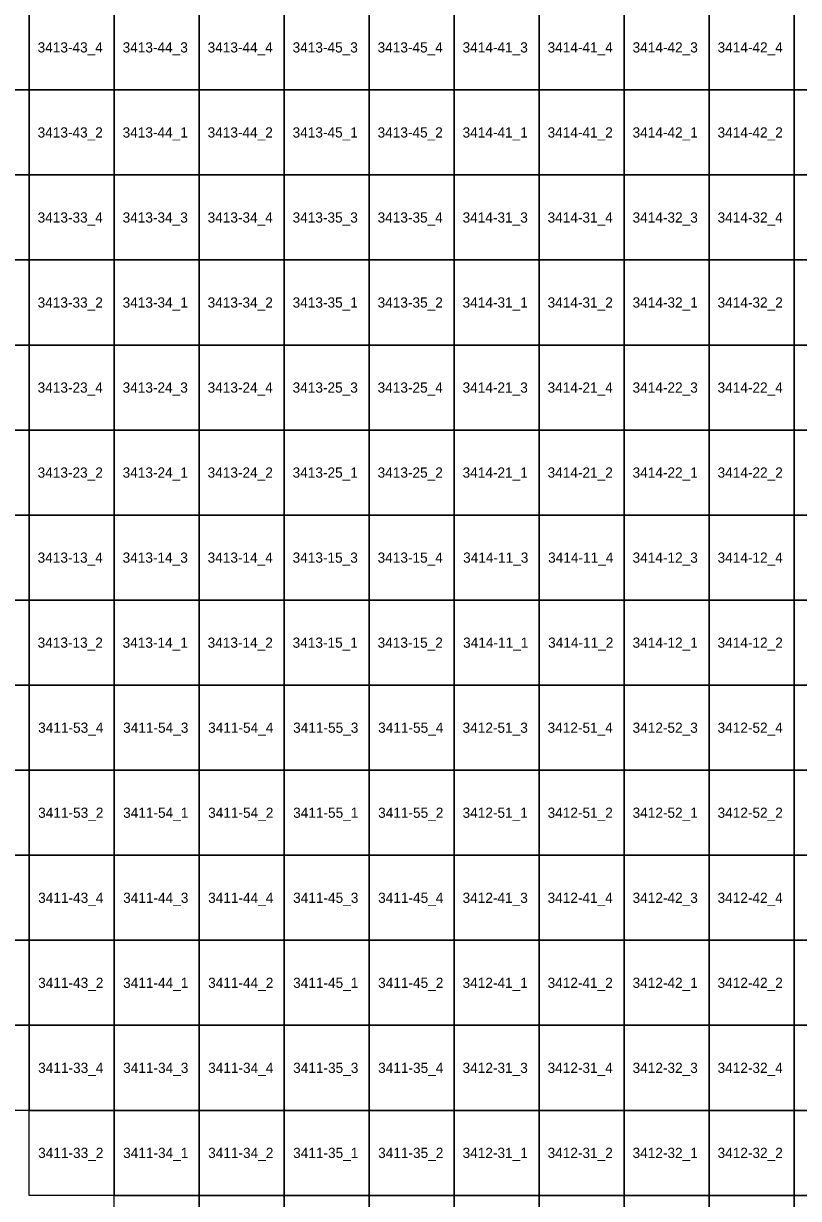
# Model space of a CAD drawing. Extents: x 312500 to 765000, y 172500 to 440000.
# Drawn here: x 612332 to 635129, y 209909 to 244452 of the extents above; entities that cross this region are included whole.
import ezdxf

# ---------------------------------------------------------------- set-up
doc = ezdxf.new("R2010")
doc.units = 0
doc.layers.add('Topo5_ramis_TKS2025', color=7, linetype='Continuous')
doc.layers.add('Topo5_ramis_TKS2025_Nr', color=7, linetype='Continuous')

msp = doc.modelspace()

# ---------------------------------------------------------------- linework, layer by layer
at = {"layer": 'Topo5_ramis_TKS2025'}
for points in [[(610000, 242500), (610000, 245000), (612500, 245000), (612500, 242500), (610000, 242500)], [(612500, 242500), (612500, 245000), (615000, 245000), (615000, 242500), (612500, 242500)], [(615000, 242500), (615000, 245000), (617500, 245000), (617500, 242500), (615000, 242500)], [(617500, 242500), (617500, 245000), (620000, 245000), (620000, 242500), (617500, 242500)], [(620000, 242500), (620000, 245000), (622500, 245000), (622500, 242500), (620000, 242500)], [(622500, 242500), (622500, 245000), (625000, 245000), (625000, 242500), (622500, 242500)], [(625000, 242500), (625000, 245000), (627500, 245000), (627500, 242500), (625000, 242500)], [(627500, 242500), (627500, 245000), (630000, 245000), (630000, 242500), (627500, 242500)], [(630000, 242500), (630000, 245000), (632500, 245000), (632500, 242500), (630000, 242500)], [(632500, 242500), (632500, 245000), (635000, 245000), (635000, 242500), (632500, 242500)], [(635000, 242500), (635000, 245000), (637500, 245000), (637500, 242500), (635000, 242500)], [(610000, 240000), (610000, 242500), (612500, 242500), (612500, 240000), (610000, 240000)], [(612500, 240000), (612500, 242500), (615000, 242500), (615000, 240000), (612500, 240000)], [(615000, 240000), (615000, 242500), (617500, 242500), (617500, 240000), (615000, 240000)], [(617500, 240000), (617500, 242500), (620000, 242500), (620000, 240000), (617500, 240000)], [(620000, 240000), (620000, 242500), (622500, 242500), (622500, 240000), (620000, 240000)], [(622500, 240000), (622500, 242500), (625000, 242500), (625000, 240000), (622500, 240000)], [(625000, 240000), (625000, 242500), (627500, 242500), (627500, 240000), (625000, 240000)], [(627500, 240000), (627500, 242500), (630000, 242500), (630000, 240000), (627500, 240000)], [(630000, 240000), (630000, 242500), (632500, 242500), (632500, 240000), (630000, 240000)], [(632500, 240000), (632500, 242500), (635000, 242500), (635000, 240000), (632500, 240000)], [(635000, 240000), (635000, 242500), (637500, 242500), (637500, 240000), (635000, 240000)], [(610000, 237500), (610000, 240000), (612500, 240000), (612500, 237500), (610000, 237500)], [(612500, 237500), (612500, 240000), (615000, 240000), (615000, 237500), (612500, 237500)], [(615000, 237500), (615000, 240000), (617500, 240000), (617500, 237500), (615000, 237500)], [(617500, 237500), (617500, 240000), (620000, 240000), (620000, 237500), (617500, 237500)], [(620000, 237500), (620000, 240000), (622500, 240000), (622500, 237500), (620000, 237500)], [(622500, 237500), (622500, 240000), (625000, 240000), (625000, 237500), (622500, 237500)], [(625000, 237500), (625000, 240000), (627500, 240000), (627500, 237500), (625000, 237500)], [(627500, 237500), (627500, 240000), (630000, 240000), (630000, 237500), (627500, 237500)], [(630000, 237500), (630000, 240000), (632500, 240000), (632500, 237500), (630000, 237500)], [(632500, 237500), (632500, 240000), (635000, 240000), (635000, 237500), (632500, 237500)], [(635000, 237500), (635000, 240000), (637500, 240000), (637500, 237500), (635000, 237500)], [(610000, 235000), (610000, 237500), (612500, 237500), (612500, 235000), (610000, 235000)], [(612500, 235000), (612500, 237500), (615000, 237500), (615000, 235000), (612500, 235000)], [(615000, 235000), (615000, 237500), (617500, 237500), (617500, 235000), (615000, 235000)], [(617500, 235000), (617500, 237500), (620000, 237500), (620000, 235000), (617500, 235000)], [(620000, 235000), (620000, 237500), (622500, 237500), (622500, 235000), (620000, 235000)], [(622500, 235000), (622500, 237500), (625000, 237500), (625000, 235000), (622500, 235000)], [(625000, 235000), (625000, 237500), (627500, 237500), (627500, 235000), (625000, 235000)], [(627500, 235000), (627500, 237500), (630000, 237500), (630000, 235000), (627500, 235000)], [(630000, 235000), (630000, 237500), (632500, 237500), (632500, 235000), (630000, 235000)], [(632500, 235000), (632500, 237500), (635000, 237500), (635000, 235000), (632500, 235000)], [(635000, 235000), (635000, 237500), (637500, 237500), (637500, 235000), (635000, 235000)], [(610000, 232500), (610000, 235000), (612500, 235000), (612500, 232500), (610000, 232500)], [(612500, 232500), (612500, 235000), (615000, 235000), (615000, 232500), (612500, 232500)], [(615000, 232500), (615000, 235000), (617500, 235000), (617500, 232500), (615000, 232500)], [(617500, 232500), (617500, 235000), (620000, 235000), (620000, 232500), (617500, 232500)], [(620000, 232500), (620000, 235000), (622500, 235000), (622500, 232500), (620000, 232500)], [(622500, 232500), (622500, 235000), (625000, 235000), (625000, 232500), (622500, 232500)], [(625000, 232500), (625000, 235000), (627500, 235000), (627500, 232500), (625000, 232500)], [(627500, 232500), (627500, 235000), (630000, 235000), (630000, 232500), (627500, 232500)], [(630000, 232500), (630000, 235000), (632500, 235000), (632500, 232500), (630000, 232500)], [(632500, 232500), (632500, 235000), (635000, 235000), (635000, 232500), (632500, 232500)], [(635000, 232500), (635000, 235000), (637500, 235000), (637500, 232500), (635000, 232500)], [(610000, 230000), (610000, 232500), (612500, 232500), (612500, 230000), (610000, 230000)], [(612500, 230000), (612500, 232500), (615000, 232500), (615000, 230000), (612500, 230000)], [(615000, 230000), (615000, 232500), (617500, 232500), (617500, 230000), (615000, 230000)], [(617500, 230000), (617500, 232500), (620000, 232500), (620000, 230000), (617500, 230000)], [(620000, 230000), (620000, 232500), (622500, 232500), (622500, 230000), (620000, 230000)], [(622500, 230000), (622500, 232500), (625000, 232500), (625000, 230000), (622500, 230000)], [(625000, 230000), (625000, 232500), (627500, 232500), (627500, 230000), (625000, 230000)], [(627500, 230000), (627500, 232500), (630000, 232500), (630000, 230000), (627500, 230000)], [(630000, 230000), (630000, 232500), (632500, 232500), (632500, 230000), (630000, 230000)], [(632500, 230000), (632500, 232500), (635000, 232500), (635000, 230000), (632500, 230000)], [(635000, 230000), (635000, 232500), (637500, 232500), (637500, 230000), (635000, 230000)], [(610000, 227500), (610000, 230000), (612500, 230000), (612500, 227500), (610000, 227500)], [(612500, 227500), (612500, 230000), (615000, 230000), (615000, 227500), (612500, 227500)], [(615000, 227500), (615000, 230000), (617500, 230000), (617500, 227500), (615000, 227500)], [(617500, 227500), (617500, 230000), (620000, 230000), (620000, 227500), (617500, 227500)], [(620000, 227500), (620000, 230000), (622500, 230000), (622500, 227500), (620000, 227500)], [(622500, 227500), (622500, 230000), (625000, 230000), (625000, 227500), (622500, 227500)], [(625000, 227500), (625000, 230000), (627500, 230000), (627500, 227500), (625000, 227500)], [(627500, 227500), (627500, 230000), (630000, 230000), (630000, 227500), (627500, 227500)], [(630000, 227500), (630000, 230000), (632500, 230000), (632500, 227500), (630000, 227500)], [(632500, 227500), (632500, 230000), (635000, 230000), (635000, 227500), (632500, 227500)], [(635000, 227500), (635000, 230000), (637500, 230000), (637500, 227500), (635000, 227500)], [(610000, 225000), (610000, 227500), (612500, 227500), (612500, 225000), (610000, 225000)], [(612500, 225000), (612500, 227500), (615000, 227500), (615000, 225000), (612500, 225000)], [(615000, 225000), (615000, 227500), (617500, 227500), (617500, 225000), (615000, 225000)], [(617500, 225000), (617500, 227500), (620000, 227500), (620000, 225000), (617500, 225000)], [(620000, 225000), (620000, 227500), (622500, 227500), (622500, 225000), (620000, 225000)], [(622500, 225000), (622500, 227500), (625000, 227500), (625000, 225000), (622500, 225000)], [(625000, 225000), (625000, 227500), (627500, 227500), (627500, 225000), (625000, 225000)], [(627500, 225000), (627500, 227500), (630000, 227500), (630000, 225000), (627500, 225000)], [(630000, 225000), (630000, 227500), (632500, 227500), (632500, 225000), (630000, 225000)], [(632500, 225000), (632500, 227500), (635000, 227500), (635000, 225000), (632500, 225000)], [(635000, 225000), (635000, 227500), (637500, 227500), (637500, 225000), (635000, 225000)], [(610000, 222500), (610000, 225000), (612500, 225000), (612500, 222500), (610000, 222500)], [(612500, 222500), (612500, 225000), (615000, 225000), (615000, 222500), (612500, 222500)], [(615000, 222500), (615000, 225000), (617500, 225000), (617500, 222500), (615000, 222500)], [(617500, 222500), (617500, 225000), (620000, 225000), (620000, 222500), (617500, 222500)], [(620000, 222500), (620000, 225000), (622500, 225000), (622500, 222500), (620000, 222500)], [(622500, 222500), (622500, 225000), (625000, 225000), (625000, 222500), (622500, 222500)], [(625000, 222500), (625000, 225000), (627500, 225000), (627500, 222500), (625000, 222500)], [(627500, 222500), (627500, 225000), (630000, 225000), (630000, 222500), (627500, 222500)], [(630000, 222500), (630000, 225000), (632500, 225000), (632500, 222500), (630000, 222500)], [(632500, 222500), (632500, 225000), (635000, 225000), (635000, 222500), (632500, 222500)], [(635000, 222500), (635000, 225000), (637500, 225000), (637500, 222500), (635000, 222500)], [(610000, 220000), (610000, 222500), (612500, 222500), (612500, 220000), (610000, 220000)], [(612500, 220000), (612500, 222500), (615000, 222500), (615000, 220000), (612500, 220000)], [(615000, 220000), (615000, 222500), (617500, 222500), (617500, 220000), (615000, 220000)], [(617500, 220000), (617500, 222500), (620000, 222500), (620000, 220000), (617500, 220000)], [(620000, 220000), (620000, 222500), (622500, 222500), (622500, 220000), (620000, 220000)], [(622500, 220000), (622500, 222500), (625000, 222500), (625000, 220000), (622500, 220000)], [(625000, 220000), (625000, 222500), (627500, 222500), (627500, 220000), (625000, 220000)], [(627500, 220000), (627500, 222500), (630000, 222500), (630000, 220000), (627500, 220000)], [(630000, 220000), (630000, 222500), (632500, 222500), (632500, 220000), (630000, 220000)], [(632500, 220000), (632500, 222500), (635000, 222500), (635000, 220000), (632500, 220000)], [(635000, 220000), (635000, 222500), (637500, 222500), (637500, 220000), (635000, 220000)], [(610000, 217500), (610000, 220000), (612500, 220000), (612500, 217500), (610000, 217500)], [(612500, 217500), (612500, 220000), (615000, 220000), (615000, 217500), (612500, 217500)], [(615000, 217500), (615000, 220000), (617500, 220000), (617500, 217500), (615000, 217500)], [(617500, 217500), (617500, 220000), (620000, 220000), (620000, 217500), (617500, 217500)], [(620000, 217500), (620000, 220000), (622500, 220000), (622500, 217500), (620000, 217500)], [(622500, 217500), (622500, 220000), (625000, 220000), (625000, 217500), (622500, 217500)], [(625000, 217500), (625000, 220000), (627500, 220000), (627500, 217500), (625000, 217500)], [(627500, 217500), (627500, 220000), (630000, 220000), (630000, 217500), (627500, 217500)], [(630000, 217500), (630000, 220000), (632500, 220000), (632500, 217500), (630000, 217500)], [(632500, 217500), (632500, 220000), (635000, 220000), (635000, 217500), (632500, 217500)], [(635000, 217500), (635000, 220000), (637500, 220000), (637500, 217500), (635000, 217500)], [(610000, 215000), (610000, 217500), (612500, 217500), (612500, 215000), (610000, 215000)], [(612500, 215000), (612500, 217500), (615000, 217500), (615000, 215000), (612500, 215000)], [(615000, 215000), (615000, 217500), (617500, 217500), (617500, 215000), (615000, 215000)], [(617500, 215000), (617500, 217500), (620000, 217500), (620000, 215000), (617500, 215000)], [(620000, 215000), (620000, 217500), (622500, 217500), (622500, 215000), (620000, 215000)], [(622500, 215000), (622500, 217500), (625000, 217500), (625000, 215000), (622500, 215000)], [(625000, 215000), (625000, 217500), (627500, 217500), (627500, 215000), (625000, 215000)], [(627500, 215000), (627500, 217500), (630000, 217500), (630000, 215000), (627500, 215000)], [(630000, 215000), (630000, 217500), (632500, 217500), (632500, 215000), (630000, 215000)], [(632500, 215000), (632500, 217500), (635000, 217500), (635000, 215000), (632500, 215000)], [(635000, 215000), (635000, 217500), (637500, 217500), (637500, 215000), (635000, 215000)], [(610000, 212500), (610000, 215000), (612500, 215000), (612500, 212500), (610000, 212500)], [(612500, 212500), (612500, 215000), (615000, 215000), (615000, 212500), (612500, 212500)], [(615000, 212500), (615000, 215000), (617500, 215000), (617500, 212500), (615000, 212500)], [(617500, 212500), (617500, 215000), (620000, 215000), (620000, 212500), (617500, 212500)], [(620000, 212500), (620000, 215000), (622500, 215000), (622500, 212500), (620000, 212500)], [(622500, 212500), (622500, 215000), (625000, 215000), (625000, 212500), (622500, 212500)], [(625000, 212500), (625000, 215000), (627500, 215000), (627500, 212500), (625000, 212500)], [(627500, 212500), (627500, 215000), (630000, 215000), (630000, 212500), (627500, 212500)], [(630000, 212500), (630000, 215000), (632500, 215000), (632500, 212500), (630000, 212500)], [(632500, 212500), (632500, 215000), (635000, 215000), (635000, 212500), (632500, 212500)], [(635000, 212500), (635000, 215000), (637500, 215000), (637500, 212500), (635000, 212500)], [(612500, 210000), (612500, 212500), (615000, 212500), (615000, 210000), (612500, 210000)], [(615000, 210000), (615000, 212500), (617500, 212500), (617500, 210000), (615000, 210000)], [(617500, 210000), (617500, 212500), (620000, 212500), (620000, 210000), (617500, 210000)], [(620000, 210000), (620000, 212500), (622500, 212500), (622500, 210000), (620000, 210000)], [(622500, 210000), (622500, 212500), (625000, 212500), (625000, 210000), (622500, 210000)], [(625000, 210000), (625000, 212500), (627500, 212500), (627500, 210000), (625000, 210000)], [(627500, 210000), (627500, 212500), (630000, 212500), (630000, 210000), (627500, 210000)], [(630000, 210000), (630000, 212500), (632500, 212500), (632500, 210000), (630000, 210000)], [(632500, 210000), (632500, 212500), (635000, 212500), (635000, 210000), (632500, 210000)], [(635000, 210000), (635000, 212500), (637500, 212500), (637500, 210000), (635000, 210000)], [(615000, 207500), (615000, 210000), (617500, 210000), (617500, 207500), (615000, 207500)], [(617500, 207500), (617500, 210000), (620000, 210000), (620000, 207500), (617500, 207500)], [(620000, 207500), (620000, 210000), (622500, 210000), (622500, 207500), (620000, 207500)], [(622500, 207500), (622500, 210000), (625000, 210000), (625000, 207500), (622500, 207500)], [(625000, 207500), (625000, 210000), (627500, 210000), (627500, 207500), (625000, 207500)], [(627500, 207500), (627500, 210000), (630000, 210000), (630000, 207500), (627500, 207500)], [(630000, 207500), (630000, 210000), (632500, 210000), (632500, 207500), (630000, 207500)], [(632500, 207500), (632500, 210000), (635000, 210000), (635000, 207500), (632500, 207500)], [(635000, 207500), (635000, 210000), (637500, 210000), (637500, 207500), (635000, 207500)]]:
    msp.add_lwpolyline(points, dxfattribs=at)

# ---------------------------------------------------------------- texts
at = {"layer": 'Topo5_ramis_TKS2025_Nr'}
for s, p in [('3413-43_4', (612748, 243600)), ('3413-44_3', (615248, 243600)), ('3413-44_4', (617748, 243600)), ('3413-45_3', (620248, 243600)), ('3413-45_4', (622748, 243600)), ('3414-41_3', (625248, 243600)), ('3414-41_4', (627748, 243600)), ('3414-42_3', (630248, 243600)), ('3414-42_4', (632748, 243600)), ('3413-43_2', (612748, 241100)), ('3413-44_1', (615248, 241100)), ('3413-44_2', (617748, 241100)), ('3413-45_1', (620248, 241100)), ('3413-45_2', (622748, 241100)), ('3414-41_1', (625248, 241100)), ('3414-41_2', (627748, 241100)), ('3414-42_1', (630248, 241100)), ('3414-42_2', (632748, 241100)), ('3413-33_4', (612748, 238600)), ('3413-34_3', (615248, 238600)), ('3413-34_4', (617748, 238600)), ('3413-35_3', (620248, 238600)), ('3413-35_4', (622748, 238600)), ('3414-31_3', (625248, 238600)), ('3414-31_4', (627748, 238600)), ('3414-32_3', (630248, 238600)), ('3414-32_4', (632748, 238600)), ('3413-33_2', (612748, 236100)), ('3413-34_1', (615248, 236100)), ('3413-34_2', (617748, 236100)), ('3413-35_1', (620248, 236100)), ('3413-35_2', (622748, 236100)), ('3414-31_1', (625248, 236100)), ('3414-31_2', (627748, 236100)), ('3414-32_1', (630248, 236100)), ('3414-32_2', (632748, 236100)), ('3413-23_4', (612748, 233600)), ('3413-24_3', (615248, 233600)), ('3413-24_4', (617748, 233600)), ('3413-25_3', (620248, 233600)), ('3413-25_4', (622748, 233600)), ('3414-21_3', (625248, 233600)), ('3414-21_4', (627748, 233600)), ('3414-22_3', (630248, 233600)), ('3414-22_4', (632748, 233600)), ('3413-23_2', (612748, 231100)), ('3413-24_1', (615248, 231100)), ('3413-24_2', (617748, 231100)), ('3413-25_1', (620248, 231100)), ('3413-25_2', (622748, 231100)), ('3414-21_1', (625248, 231100)), ('3414-21_2', (627748, 231100)), ('3414-22_1', (630248, 231100)), ('3414-22_2', (632748, 231100)), ('3413-13_4', (612748, 228600)), ('3413-14_3', (615248, 228600)), ('3413-14_4', (617748, 228600)), ('3413-15_3', (620248, 228600)), ('3413-15_4', (622748, 228600)), ('3414-11_3', (625264, 228600)), ('3414-11_4', (627764, 228600)), ('3414-12_3', (630248, 228600)), ('3414-12_4', (632748, 228600)), ('3413-13_2', (612748, 226100)), ('3413-14_1', (615248, 226100)), ('3413-14_2', (617748, 226100)), ('3413-15_1', (620248, 226100)), ('3413-15_2', (622748, 226100)), ('3414-11_1', (625264, 226100)), ('3414-11_2', (627764, 226100)), ('3414-12_1', (630248, 226100)), ('3414-12_2', (632748, 226100)), ('3411-53_4', (612764, 223600)), ('3411-54_3', (615264, 223600)), ('3411-54_4', (617764, 223600)), ('3411-55_3', (620264, 223600)), ('3411-55_4', (622764, 223600)), ('3412-51_3', (625248, 223600)), ('3412-51_4', (627748, 223600)), ('3412-52_3', (630248, 223600)), ('3412-52_4', (632748, 223600)), ('3411-53_2', (612764, 221100)), ('3411-54_1', (615264, 221100)), ('3411-54_2', (617764, 221100)), ('3411-55_1', (620264, 221100)), ('3411-55_2', (622764, 221100)), ('3412-51_1', (625248, 221100)), ('3412-51_2', (627748, 221100)), ('3412-52_1', (630248, 221100)), ('3412-52_2', (632748, 221100)), ('3411-43_4', (612764, 218600)), ('3411-44_3', (615264, 218600)), ('3411-44_4', (617764, 218600)), ('3411-45_3', (620264, 218600)), ('3411-45_4', (622764, 218600)), ('3412-41_3', (625248, 218600)), ('3412-41_4', (627748, 218600)), ('3412-42_3', (630248, 218600)), ('3412-42_4', (632748, 218600)), ('3411-43_2', (612764, 216100)), ('3411-44_1', (615264, 216100)), ('3411-44_2', (617764, 216100)), ('3411-45_1', (620264, 216100)), ('3411-45_2', (622764, 216100)), ('3412-41_1', (625248, 216100)), ('3412-41_2', (627748, 216100)), ('3412-42_1', (630248, 216100)), ('3412-42_2', (632748, 216100)), ('3411-33_4', (612764, 213600)), ('3411-34_3', (615264, 213600)), ('3411-34_4', (617764, 213600)), ('3411-35_3', (620264, 213600)), ('3411-35_4', (622764, 213600)), ('3412-31_3', (625248, 213600)), ('3412-31_4', (627748, 213600)), ('3412-32_3', (630248, 213600)), ('3412-32_4', (632748, 213600)), ('3411-33_2', (612764, 211100)), ('3411-34_1', (615264, 211100)), ('3411-34_2', (617764, 211100)), ('3411-35_1', (620264, 211100)), ('3411-35_2', (622764, 211100)), ('3412-31_1', (625248, 211100)), ('3412-31_2', (627748, 211100)), ('3412-32_1', (630248, 211100)), ('3412-32_2', (632748, 211100))]:
    msp.add_text(s, height=300, dxfattribs=at).set_placement(p)

doc.saveas('drawing.dxf')
